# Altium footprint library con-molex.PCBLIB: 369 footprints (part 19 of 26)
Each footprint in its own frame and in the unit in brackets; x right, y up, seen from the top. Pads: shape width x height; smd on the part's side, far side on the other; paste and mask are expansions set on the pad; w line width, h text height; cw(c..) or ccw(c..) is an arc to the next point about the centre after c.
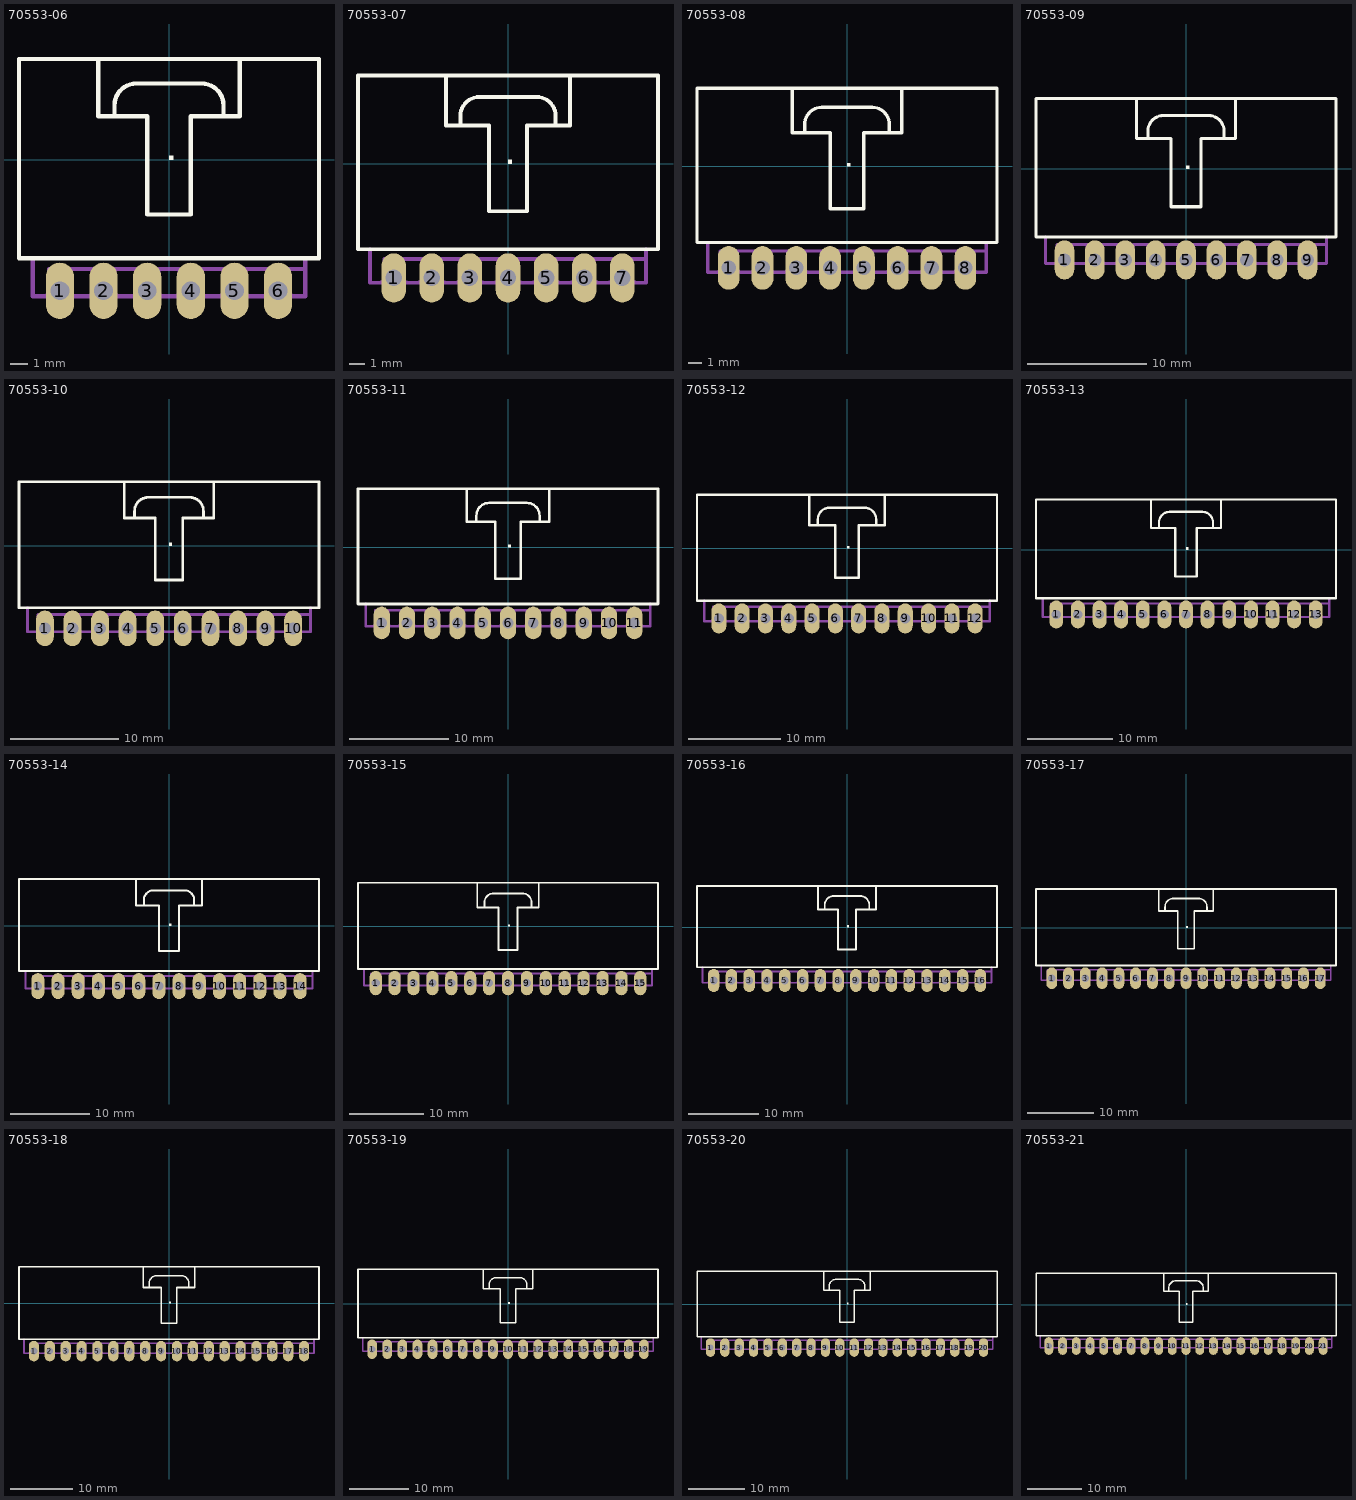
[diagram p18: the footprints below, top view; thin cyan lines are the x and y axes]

## 70553-06 [mil]
pads (6):
  oval 64.5x129 hole 43: 1(-250,-300) 2(-150,-300) 3(-50,-300) 4(50,-300) 5(150,-300) 6(250,-300)
Top Overlay:
  region: 0,0 10,0 10,10 0,10
  lines w10: -162.5,231.25 -162.5,100 -125,100 ; -125,100 -50,100 -50,-125 50,-125 50,100 125,100 ; -125,100 -125,125 cw(c-75,125) -75,175 75,175 cw(c75,125) 125,125 125,100 ; 125,100 162.5,100 162.5,231.25 ; 162.5,231.25 343.75,231.25 343.75,-225 -343.75,-225 -343.75,231.25 162.5,231.25
Mechanical 16:
  rectangle: -262.5,-300 -237.5,-250
  rectangle: -162.5,-300 -137.5,-250
  rectangle: -62.5,-300 -37.5,-250
  rectangle: 37.5,-300 62.5,-250
  rectangle: 137.5,-300 162.5,-250
  rectangle: 237.5,-300 262.5,-250
  lines w5: -275,-250 -225,-250 ; -175,-250 -125,-250 ; -75,-250 -25,-250 ; 25,-250 75,-250 ; 125,-250 175,-250 ; 225,-250 275,-250
  lines w10: -312.5,-225 -312.5,-312.5 -285,-312.5 ccw(c-285,-302.5) -275,-302.5 -275,-250 ; 312.5,-225 312.5,-250 ; 312.5,-250 312.5,-312.5 285,-312.5 cw(c285,-302.5) 275,-302.5 275,-250 312.5,-250 ; -225,-302.5 -225,-250 -175,-250 -175,-302.5 cw(c-185,-302.5) -185,-312.5 -215,-312.5 cw(c-215,-302.5) -225,-302.5 ; -125,-302.5 -125,-250 -75,-250 -75,-302.5 cw(c-85,-302.5) -85,-312.5 -115,-312.5 cw(c-115,-302.5) -125,-302.5 ; -25,-302.5 -25,-250 25,-250 25,-302.5 cw(c15,-302.5) 15,-312.5 -15,-312.5 cw(c-15,-302.5) -25,-302.5 ; 75,-302.5 75,-250 125,-250 125,-302.5 cw(c115,-302.5) 115,-312.5 85,-312.5 cw(c85,-302.5) 75,-302.5 ; 175,-302.5 175,-250 225,-250 225,-302.5 cw(c215,-302.5) 215,-312.5 185,-312.5 cw(c185,-302.5) 175,-302.5

## 70553-07 [mil]
pads (7):
  oval 64.5x129 hole 43: 1(-300,-300) 2(-200,-300) 3(-100,-300) 4(0,-300) 5(100,-300) 6(200,-300) 7(300,-300)
Top Overlay:
  region: 0,0 10,0 10,10 0,10
  lines w10: -162.5,231.25 -162.5,100 -125,100 ; -125,100 -50,100 -50,-125 50,-125 50,100 125,100 ; -125,100 -125,125 cw(c-75,125) -75,175 75,175 cw(c75,125) 125,125 125,100 ; 125,100 162.5,100 162.5,231.25 ; 162.5,231.25 393.75,231.25 393.75,-225 -393.75,-225 -393.75,231.25 162.5,231.25
Mechanical 16:
  rectangle: -312.5,-300 -287.5,-250
  rectangle: -212.5,-300 -187.5,-250
  rectangle: -112.5,-300 -87.5,-250
  rectangle: -12.5,-300 12.5,-250
  rectangle: 87.5,-300 112.5,-250
  rectangle: 187.5,-300 212.5,-250
  rectangle: 287.5,-300 312.5,-250
  lines w5: -325,-250 -275,-250 ; -225,-250 -175,-250 ; -125,-250 -75,-250 ; -25,-250 25,-250 ; 75,-250 125,-250 ; 175,-250 225,-250 ; 275,-250 325,-250
  lines w10: -362.5,-225 -362.5,-312.5 -335,-312.5 ccw(c-335,-302.5) -325,-302.5 -325,-250 ; 362.5,-225 362.5,-250 ; 362.5,-250 362.5,-312.5 335,-312.5 cw(c335,-302.5) 325,-302.5 325,-250 362.5,-250 ; -275,-302.5 -275,-250 -225,-250 -225,-302.5 cw(c-235,-302.5) -235,-312.5 -265,-312.5 cw(c-265,-302.5) -275,-302.5 ; -175,-302.5 -175,-250 -125,-250 -125,-302.5 cw(c-135,-302.5) -135,-312.5 -165,-312.5 cw(c-165,-302.5) -175,-302.5 ; -75,-302.5 -75,-250 -25,-250 -25,-302.5 cw(c-35,-302.5) -35,-312.5 -65,-312.5 cw(c-65,-302.5) -75,-302.5 ; 25,-302.5 25,-250 75,-250 75,-302.5 cw(c65,-302.5) 65,-312.5 35,-312.5 cw(c35,-302.5) 25,-302.5 ; 125,-302.5 125,-250 175,-250 175,-302.5 cw(c165,-302.5) 165,-312.5 135,-312.5 cw(c135,-302.5) 125,-302.5 ; 225,-302.5 225,-250 275,-250 275,-302.5 cw(c265,-302.5) 265,-312.5 235,-312.5 cw(c235,-302.5) 225,-302.5

## 70553-08 [mil]
pads (8):
  oval 64.5x129 hole 43: 1(-350,-300) 2(-250,-300) 3(-150,-300) 4(-50,-300) 5(50,-300) 6(150,-300) 7(250,-300) 8(350,-300)
Top Overlay:
  region: 0,0 10,0 10,10 0,10
  lines w10: -162.5,231.25 -162.5,100 -125,100 ; -125,100 -50,100 -50,-125 50,-125 50,100 125,100 ; -125,100 -125,125 cw(c-75,125) -75,175 75,175 cw(c75,125) 125,125 125,100 ; 125,100 162.5,100 162.5,231.25 ; 162.5,231.25 443.75,231.25 443.75,-225 -443.75,-225 -443.75,231.25 162.5,231.25
Mechanical 16:
  rectangle: -362.5,-300 -337.5,-250
  rectangle: -262.5,-300 -237.5,-250
  rectangle: -162.5,-300 -137.5,-250
  rectangle: -62.5,-300 -37.5,-250
  rectangle: 37.5,-300 62.5,-250
  rectangle: 137.5,-300 162.5,-250
  rectangle: 237.5,-300 262.5,-250
  rectangle: 337.5,-300 362.5,-250
  lines w5: -375,-250 -325,-250 ; -275,-250 -225,-250 ; -175,-250 -125,-250 ; -75,-250 -25,-250 ; 25,-250 75,-250 ; 125,-250 175,-250 ; 225,-250 275,-250 ; 325,-250 375,-250
  lines w10: -412.5,-225 -412.5,-312.5 -385,-312.5 ccw(c-385,-302.5) -375,-302.5 -375,-250 ; 412.5,-225 412.5,-250 ; 412.5,-250 412.5,-312.5 385,-312.5 cw(c385,-302.5) 375,-302.5 375,-250 412.5,-250 ; -325,-302.5 -325,-250 -275,-250 -275,-302.5 cw(c-285,-302.5) -285,-312.5 -315,-312.5 cw(c-315,-302.5) -325,-302.5 ; -225,-302.5 -225,-250 -175,-250 -175,-302.5 cw(c-185,-302.5) -185,-312.5 -215,-312.5 cw(c-215,-302.5) -225,-302.5 ; -125,-302.5 -125,-250 -75,-250 -75,-302.5 cw(c-85,-302.5) -85,-312.5 -115,-312.5 cw(c-115,-302.5) -125,-302.5 ; -25,-302.5 -25,-250 25,-250 25,-302.5 cw(c15,-302.5) 15,-312.5 -15,-312.5 cw(c-15,-302.5) -25,-302.5 ; 75,-302.5 75,-250 125,-250 125,-302.5 cw(c115,-302.5) 115,-312.5 85,-312.5 cw(c85,-302.5) 75,-302.5 ; 175,-302.5 175,-250 225,-250 225,-302.5 cw(c215,-302.5) 215,-312.5 185,-312.5 cw(c185,-302.5) 175,-302.5 ; 275,-302.5 275,-250 325,-250 325,-302.5 cw(c315,-302.5) 315,-312.5 285,-312.5 cw(c285,-302.5) 275,-302.5

## 70553-09 [mil]
pads (9):
  oval 64.5x129 hole 43: 1(-400,-300) 2(-300,-300) 3(-200,-300) 4(-100,-300) 5(0,-300) 6(100,-300) 7(200,-300) 8(300,-300) 9(400,-300)
Top Overlay:
  region: 0,0 10,0 10,10 0,10
  lines w10: -162.5,231.25 -162.5,100 -125,100 ; -125,100 -50,100 -50,-125 50,-125 50,100 125,100 ; -125,100 -125,125 cw(c-75,125) -75,175 75,175 cw(c75,125) 125,125 125,100 ; 125,100 162.5,100 162.5,231.25 ; 162.5,231.25 493.75,231.25 493.75,-225 -493.75,-225 -493.75,231.25 162.5,231.25
Mechanical 16:
  rectangle: -412.5,-300 -387.5,-250
  rectangle: -312.5,-300 -287.5,-250
  rectangle: -212.5,-300 -187.5,-250
  rectangle: -112.5,-300 -87.5,-250
  rectangle: -12.5,-300 12.5,-250
  rectangle: 87.5,-300 112.5,-250
  rectangle: 187.5,-300 212.5,-250
  rectangle: 287.5,-300 312.5,-250
  rectangle: 387.5,-300 412.5,-250
  lines w5: -425,-250 -375,-250 ; -325,-250 -275,-250 ; -225,-250 -175,-250 ; -125,-250 -75,-250 ; -25,-250 25,-250 ; 75,-250 125,-250 ; 175,-250 225,-250 ; 275,-250 325,-250 ; 375,-250 425,-250
  lines w10: -462.5,-225 -462.5,-312.5 -435,-312.5 ccw(c-435,-302.5) -425,-302.5 -425,-250 ; 462.5,-225 462.5,-250 ; 462.5,-250 462.5,-312.5 435,-312.5 cw(c435,-302.5) 425,-302.5 425,-250 462.5,-250 ; -375,-302.5 -375,-250 -325,-250 -325,-302.5 cw(c-335,-302.5) -335,-312.5 -365,-312.5 cw(c-365,-302.5) -375,-302.5 ; -275,-302.5 -275,-250 -225,-250 -225,-302.5 cw(c-235,-302.5) -235,-312.5 -265,-312.5 cw(c-265,-302.5) -275,-302.5 ; -175,-302.5 -175,-250 -125,-250 -125,-302.5 cw(c-135,-302.5) -135,-312.5 -165,-312.5 cw(c-165,-302.5) -175,-302.5 ; -75,-302.5 -75,-250 -25,-250 -25,-302.5 cw(c-35,-302.5) -35,-312.5 -65,-312.5 cw(c-65,-302.5) -75,-302.5 ; 25,-302.5 25,-250 75,-250 75,-302.5 cw(c65,-302.5) 65,-312.5 35,-312.5 cw(c35,-302.5) 25,-302.5 ; 125,-302.5 125,-250 175,-250 175,-302.5 cw(c165,-302.5) 165,-312.5 135,-312.5 cw(c135,-302.5) 125,-302.5 ; 225,-302.5 225,-250 275,-250 275,-302.5 cw(c265,-302.5) 265,-312.5 235,-312.5 cw(c235,-302.5) 225,-302.5 ; 325,-302.5 325,-250 375,-250 375,-302.5 cw(c365,-302.5) 365,-312.5 335,-312.5 cw(c335,-302.5) 325,-302.5

## 70553-10 [mil]
pads (10):
  oval 64.5x129 hole 43: 1(-450,-300) 2(-350,-300) 3(-250,-300) 4(-150,-300) 5(-50,-300) 6(50,-300) 7(150,-300) 8(250,-300) 9(350,-300) 10(450,-300)
Top Overlay:
  region: 0,0 10,0 10,10 0,10
  lines w10: -162.5,231.25 -162.5,100 -125,100 ; -125,100 -50,100 -50,-125 50,-125 50,100 125,100 ; -125,100 -125,125 cw(c-75,125) -75,175 75,175 cw(c75,125) 125,125 125,100 ; 125,100 162.5,100 162.5,231.25 ; 162.5,231.25 543.75,231.25 543.75,-225 -543.75,-225 -543.75,231.25 162.5,231.25
Mechanical 16:
  rectangle: -462.5,-300 -437.5,-250
  rectangle: -362.5,-300 -337.5,-250
  rectangle: -262.5,-300 -237.5,-250
  rectangle: -162.5,-300 -137.5,-250
  rectangle: -62.5,-300 -37.5,-250
  rectangle: 37.5,-300 62.5,-250
  rectangle: 137.5,-300 162.5,-250
  rectangle: 237.5,-300 262.5,-250
  rectangle: 337.5,-300 362.5,-250
  rectangle: 437.5,-300 462.5,-250
  lines w5: -475,-250 -425,-250 ; -375,-250 -325,-250 ; -275,-250 -225,-250 ; -175,-250 -125,-250 ; -75,-250 -25,-250 ; 25,-250 75,-250 ; 125,-250 175,-250 ; 225,-250 275,-250 ; 325,-250 375,-250 ; 425,-250 475,-250
  lines w10: -512.5,-225 -512.5,-312.5 -485,-312.5 ccw(c-485,-302.5) -475,-302.5 -475,-250 ; 512.5,-225 512.5,-250 ; 512.5,-250 512.5,-312.5 485,-312.5 cw(c485,-302.5) 475,-302.5 475,-250 512.5,-250 ; -425,-302.5 -425,-250 -375,-250 -375,-302.5 cw(c-385,-302.5) -385,-312.5 -415,-312.5 cw(c-415,-302.5) -425,-302.5 ; -325,-302.5 -325,-250 -275,-250 -275,-302.5 cw(c-285,-302.5) -285,-312.5 -315,-312.5 cw(c-315,-302.5) -325,-302.5 ; -225,-302.5 -225,-250 -175,-250 -175,-302.5 cw(c-185,-302.5) -185,-312.5 -215,-312.5 cw(c-215,-302.5) -225,-302.5 ; -125,-302.5 -125,-250 -75,-250 -75,-302.5 cw(c-85,-302.5) -85,-312.5 -115,-312.5 cw(c-115,-302.5) -125,-302.5 ; -25,-302.5 -25,-250 25,-250 25,-302.5 cw(c15,-302.5) 15,-312.5 -15,-312.5 cw(c-15,-302.5) -25,-302.5 ; 75,-302.5 75,-250 125,-250 125,-302.5 cw(c115,-302.5) 115,-312.5 85,-312.5 cw(c85,-302.5) 75,-302.5 ; 175,-302.5 175,-250 225,-250 225,-302.5 cw(c215,-302.5) 215,-312.5 185,-312.5 cw(c185,-302.5) 175,-302.5 ; 275,-302.5 275,-250 325,-250 325,-302.5 cw(c315,-302.5) 315,-312.5 285,-312.5 cw(c285,-302.5) 275,-302.5 ; 375,-302.5 375,-250 425,-250 425,-302.5 cw(c415,-302.5) 415,-312.5 385,-312.5 cw(c385,-302.5) 375,-302.5

## 70553-11 [mil]
pads (11):
  oval 64.5x129 hole 43: 1(-500,-300) 2(-400,-300) 3(-300,-300) 4(-200,-300) 5(-100,-300) 6(0,-300) 7(100,-300) 8(200,-300) 9(300,-300) 10(400,-300) 11(500,-300)
Top Overlay:
  region: 0,0 10,0 10,10 0,10
  lines w10: -162.5,231.25 -162.5,100 -125,100 ; -125,100 -50,100 -50,-125 50,-125 50,100 125,100 ; -125,100 -125,125 cw(c-75,125) -75,175 75,175 cw(c75,125) 125,125 125,100 ; 125,100 162.5,100 162.5,231.25 ; 162.5,231.25 593.75,231.25 593.75,-225 -593.75,-225 -593.75,231.25 162.5,231.25
Mechanical 16:
  rectangle: -512.5,-300 -487.5,-250
  rectangle: -412.5,-300 -387.5,-250
  rectangle: -312.5,-300 -287.5,-250
  rectangle: -212.5,-300 -187.5,-250
  rectangle: -112.5,-300 -87.5,-250
  rectangle: -12.5,-300 12.5,-250
  rectangle: 87.5,-300 112.5,-250
  rectangle: 187.5,-300 212.5,-250
  rectangle: 287.5,-300 312.5,-250
  rectangle: 387.5,-300 412.5,-250
  rectangle: 487.5,-300 512.5,-250
  lines w5: -525,-250 -475,-250 ; -425,-250 -375,-250 ; -325,-250 -275,-250 ; -225,-250 -175,-250 ; -125,-250 -75,-250 ; -25,-250 25,-250 ; 75,-250 125,-250 ; 175,-250 225,-250 ; 275,-250 325,-250 ; 375,-250 425,-250 ; 475,-250 525,-250
  lines w10: -562.5,-225 -562.5,-312.5 -535,-312.5 ccw(c-535,-302.5) -525,-302.5 -525,-250 ; 562.5,-225 562.5,-250 ; 562.5,-250 562.5,-312.5 535,-312.5 cw(c535,-302.5) 525,-302.5 525,-250 562.5,-250 ; -475,-302.5 -475,-250 -425,-250 -425,-302.5 cw(c-435,-302.5) -435,-312.5 -465,-312.5 cw(c-465,-302.5) -475,-302.5 ; -375,-302.5 -375,-250 -325,-250 -325,-302.5 cw(c-335,-302.5) -335,-312.5 -365,-312.5 cw(c-365,-302.5) -375,-302.5 ; -275,-302.5 -275,-250 -225,-250 -225,-302.5 cw(c-235,-302.5) -235,-312.5 -265,-312.5 cw(c-265,-302.5) -275,-302.5 ; -175,-302.5 -175,-250 -125,-250 -125,-302.5 cw(c-135,-302.5) -135,-312.5 -165,-312.5 cw(c-165,-302.5) -175,-302.5 ; -75,-302.5 -75,-250 -25,-250 -25,-302.5 cw(c-35,-302.5) -35,-312.5 -65,-312.5 cw(c-65,-302.5) -75,-302.5 ; 25,-302.5 25,-250 75,-250 75,-302.5 cw(c65,-302.5) 65,-312.5 35,-312.5 cw(c35,-302.5) 25,-302.5 ; 125,-302.5 125,-250 175,-250 175,-302.5 cw(c165,-302.5) 165,-312.5 135,-312.5 cw(c135,-302.5) 125,-302.5 ; 225,-302.5 225,-250 275,-250 275,-302.5 cw(c265,-302.5) 265,-312.5 235,-312.5 cw(c235,-302.5) 225,-302.5 ; 325,-302.5 325,-250 375,-250 375,-302.5 cw(c365,-302.5) 365,-312.5 335,-312.5 cw(c335,-302.5) 325,-302.5 ; 425,-302.5 425,-250 475,-250 475,-302.5 cw(c465,-302.5) 465,-312.5 435,-312.5 cw(c435,-302.5) 425,-302.5

## 70553-12 [mil]
pads (12):
  oval 64.5x129 hole 43: 1(-550,-300) 2(-450,-300) 3(-350,-300) 4(-250,-300) 5(-150,-300) 6(-50,-300) 7(50,-300) 8(150,-300) 9(250,-300) 10(350,-300) 11(450,-300) 12(550,-300)
Top Overlay:
  region: 0,0 10,0 10,10 0,10
  lines w10: -162.5,231.25 -162.5,100 -125,100 ; -125,100 -50,100 -50,-125 50,-125 50,100 125,100 ; -125,100 -125,125 cw(c-75,125) -75,175 75,175 cw(c75,125) 125,125 125,100 ; 125,100 162.5,100 162.5,231.25 ; 162.5,231.25 643.75,231.25 643.75,-225 -643.75,-225 -643.75,231.25 162.5,231.25
Mechanical 16:
  rectangle: -562.5,-300 -537.5,-250
  rectangle: -462.5,-300 -437.5,-250
  rectangle: -362.5,-300 -337.5,-250
  rectangle: -262.5,-300 -237.5,-250
  rectangle: -162.5,-300 -137.5,-250
  rectangle: -62.5,-300 -37.5,-250
  rectangle: 37.5,-300 62.5,-250
  rectangle: 137.5,-300 162.5,-250
  rectangle: 237.5,-300 262.5,-250
  rectangle: 337.5,-300 362.5,-250
  rectangle: 437.5,-300 462.5,-250
  rectangle: 537.5,-300 562.5,-250
  lines w5: -575,-250 -525,-250 ; -475,-250 -425,-250 ; -375,-250 -325,-250 ; -275,-250 -225,-250 ; -175,-250 -125,-250 ; -75,-250 -25,-250 ; 25,-250 75,-250 ; 125,-250 175,-250 ; 225,-250 275,-250 ; 325,-250 375,-250 ; 425,-250 475,-250 ; 525,-250 575,-250
  lines w10: -612.5,-225 -612.5,-312.5 -585,-312.5 ccw(c-585,-302.5) -575,-302.5 -575,-250 ; 612.5,-225 612.5,-250 ; 612.5,-250 612.5,-312.5 585,-312.5 cw(c585,-302.5) 575,-302.5 575,-250 612.5,-250 ; -525,-302.5 -525,-250 -475,-250 -475,-302.5 cw(c-485,-302.5) -485,-312.5 -515,-312.5 cw(c-515,-302.5) -525,-302.5 ; -425,-302.5 -425,-250 -375,-250 -375,-302.5 cw(c-385,-302.5) -385,-312.5 -415,-312.5 cw(c-415,-302.5) -425,-302.5 ; -325,-302.5 -325,-250 -275,-250 -275,-302.5 cw(c-285,-302.5) -285,-312.5 -315,-312.5 cw(c-315,-302.5) -325,-302.5 ; -225,-302.5 -225,-250 -175,-250 -175,-302.5 cw(c-185,-302.5) -185,-312.5 -215,-312.5 cw(c-215,-302.5) -225,-302.5 ; -125,-302.5 -125,-250 -75,-250 -75,-302.5 cw(c-85,-302.5) -85,-312.5 -115,-312.5 cw(c-115,-302.5) -125,-302.5 ; -25,-302.5 -25,-250 25,-250 25,-302.5 cw(c15,-302.5) 15,-312.5 -15,-312.5 cw(c-15,-302.5) -25,-302.5 ; 75,-302.5 75,-250 125,-250 125,-302.5 cw(c115,-302.5) 115,-312.5 85,-312.5 cw(c85,-302.5) 75,-302.5 ; 175,-302.5 175,-250 225,-250 225,-302.5 cw(c215,-302.5) 215,-312.5 185,-312.5 cw(c185,-302.5) 175,-302.5 ; 275,-302.5 275,-250 325,-250 325,-302.5 cw(c315,-302.5) 315,-312.5 285,-312.5 cw(c285,-302.5) 275,-302.5 ; 375,-302.5 375,-250 425,-250 425,-302.5 cw(c415,-302.5) 415,-312.5 385,-312.5 cw(c385,-302.5) 375,-302.5 ; 475,-302.5 475,-250 525,-250 525,-302.5 cw(c515,-302.5) 515,-312.5 485,-312.5 cw(c485,-302.5) 475,-302.5

## 70553-13 [mil]
pads (13):
  oval 64.5x129 hole 43: 1(-600,-300) 2(-500,-300) 3(-400,-300) 4(-300,-300) 5(-200,-300) 6(-100,-300) 7(0,-300) 8(100,-300) 9(200,-300) 10(300,-300) 11(400,-300) 12(500,-300) 13(600,-300)
Top Overlay:
  region: 0,0 10,0 10,10 0,10
  lines w10: -162.5,231.25 -162.5,100 -125,100 ; -125,100 -50,100 -50,-125 50,-125 50,100 125,100 ; -125,100 -125,125 cw(c-75,125) -75,175 75,175 cw(c75,125) 125,125 125,100 ; 125,100 162.5,100 162.5,231.25 ; 162.5,231.25 693.75,231.25 693.75,-225 -693.75,-225 -693.75,231.25 162.5,231.25
Mechanical 16:
  rectangle: -612.5,-300 -587.5,-250
  rectangle: -512.5,-300 -487.5,-250
  rectangle: -412.5,-300 -387.5,-250
  rectangle: -312.5,-300 -287.5,-250
  rectangle: -212.5,-300 -187.5,-250
  rectangle: -112.5,-300 -87.5,-250
  rectangle: -12.5,-300 12.5,-250
  rectangle: 87.5,-300 112.5,-250
  rectangle: 187.5,-300 212.5,-250
  rectangle: 287.5,-300 312.5,-250
  rectangle: 587.5,-300 612.5,-250
  rectangle: 387.5,-300 412.5,-250
  rectangle: 487.5,-300 512.5,-250
  lines w5: -625,-250 -575,-250 ; -525,-250 -475,-250 ; -425,-250 -375,-250 ; -325,-250 -275,-250 ; -225,-250 -175,-250 ; -125,-250 -75,-250 ; -25,-250 25,-250 ; 75,-250 125,-250 ; 175,-250 225,-250 ; 275,-250 325,-250 ; 375,-250 425,-250 ; 475,-250 525,-250 ; 575,-250 625,-250
  lines w10: -662.5,-225 -662.5,-312.5 -635,-312.5 ccw(c-635,-302.5) -625,-302.5 -625,-250 ; 662.5,-225 662.5,-250 ; 662.5,-250 662.5,-312.5 635,-312.5 cw(c635,-302.5) 625,-302.5 625,-250 662.5,-250 ; -575,-302.5 -575,-250 -525,-250 -525,-302.5 cw(c-535,-302.5) -535,-312.5 -565,-312.5 cw(c-565,-302.5) -575,-302.5 ; -475,-302.5 -475,-250 -425,-250 -425,-302.5 cw(c-435,-302.5) -435,-312.5 -465,-312.5 cw(c-465,-302.5) -475,-302.5 ; -375,-302.5 -375,-250 -325,-250 -325,-302.5 cw(c-335,-302.5) -335,-312.5 -365,-312.5 cw(c-365,-302.5) -375,-302.5 ; -275,-302.5 -275,-250 -225,-250 -225,-302.5 cw(c-235,-302.5) -235,-312.5 -265,-312.5 cw(c-265,-302.5) -275,-302.5 ; -175,-302.5 -175,-250 -125,-250 -125,-302.5 cw(c-135,-302.5) -135,-312.5 -165,-312.5 cw(c-165,-302.5) -175,-302.5 ; -75,-302.5 -75,-250 -25,-250 -25,-302.5 cw(c-35,-302.5) -35,-312.5 -65,-312.5 cw(c-65,-302.5) -75,-302.5 ; 25,-302.5 25,-250 75,-250 75,-302.5 cw(c65,-302.5) 65,-312.5 35,-312.5 cw(c35,-302.5) 25,-302.5 ; 125,-302.5 125,-250 175,-250 175,-302.5 cw(c165,-302.5) 165,-312.5 135,-312.5 cw(c135,-302.5) 125,-302.5 ; 225,-302.5 225,-250 275,-250 275,-302.5 cw(c265,-302.5) 265,-312.5 235,-312.5 cw(c235,-302.5) 225,-302.5 ; 325,-302.5 325,-250 375,-250 375,-302.5 cw(c365,-302.5) 365,-312.5 335,-312.5 cw(c335,-302.5) 325,-302.5 ; 425,-302.5 425,-250 475,-250 475,-302.5 cw(c465,-302.5) 465,-312.5 435,-312.5 cw(c435,-302.5) 425,-302.5 ; 525,-302.5 525,-250 575,-250 575,-302.5 cw(c565,-302.5) 565,-312.5 535,-312.5 cw(c535,-302.5) 525,-302.5

## 70553-14 [mil]
pads (14):
  oval 64.5x129 hole 43: 1(-650,-300) 2(-550,-300) 3(-450,-300) 4(-350,-300) 5(-250,-300) 6(-150,-300) 7(-50,-300) 8(50,-300) 9(150,-300) 10(250,-300) 11(350,-300) 12(450,-300) 13(550,-300) 14(650,-300)
Top Overlay:
  region: 0,0 10,0 10,10 0,10
  lines w10: -162.5,231.25 -162.5,100 -125,100 ; -125,100 -50,100 -50,-125 50,-125 50,100 125,100 ; -125,100 -125,125 cw(c-75,125) -75,175 75,175 cw(c75,125) 125,125 125,100 ; 125,100 162.5,100 162.5,231.25 ; 162.5,231.25 743.75,231.25 743.75,-225 -743.75,-225 -743.75,231.25 162.5,231.25
Mechanical 16:
  rectangle: -662.5,-300 -637.5,-250
  rectangle: -562.5,-300 -537.5,-250
  rectangle: -462.5,-300 -437.5,-250
  rectangle: -362.5,-300 -337.5,-250
  rectangle: -262.5,-300 -237.5,-250
  rectangle: -162.5,-300 -137.5,-250
  rectangle: -62.5,-300 -37.5,-250
  rectangle: 37.5,-300 62.5,-250
  rectangle: 137.5,-300 162.5,-250
  rectangle: 237.5,-300 262.5,-250
  rectangle: 637.5,-300 662.5,-250
  rectangle: 337.5,-300 362.5,-250
  rectangle: 437.5,-300 462.5,-250
  rectangle: 537.5,-300 562.5,-250
  lines w5: -675,-250 -625,-250 ; -575,-250 -525,-250 ; -475,-250 -425,-250 ; -375,-250 -325,-250 ; -275,-250 -225,-250 ; -175,-250 -125,-250 ; -75,-250 -25,-250 ; 25,-250 75,-250 ; 125,-250 175,-250 ; 225,-250 275,-250 ; 325,-250 375,-250 ; 525,-250 575,-250 ; 625,-250 675,-250
  lines w10: -712.5,-225 -712.5,-312.5 -685,-312.5 ccw(c-685,-302.5) -675,-302.5 -675,-250 ; 712.5,-225 712.5,-250 ; 425,-250 375,-250 375,-302.5 ccw(c385,-302.5) 385,-312.5 415,-312.5 ccw(c415,-302.5) 425,-302.5 425,-250 ; 425,-250 475,-250 ; 475,-250 525,-250 525,-302.5 cw(c515,-302.5) 515,-312.5 485,-312.5 cw(c485,-302.5) 475,-302.5 475,-250 ; 712.5,-250 712.5,-312.5 685,-312.5 cw(c685,-302.5) 675,-302.5 675,-250 712.5,-250 ; -625,-302.5 -625,-250 -575,-250 -575,-302.5 cw(c-585,-302.5) -585,-312.5 -615,-312.5 cw(c-615,-302.5) -625,-302.5 ; -525,-302.5 -525,-250 -475,-250 -475,-302.5 cw(c-485,-302.5) -485,-312.5 -515,-312.5 cw(c-515,-302.5) -525,-302.5 ; -425,-302.5 -425,-250 -375,-250 -375,-302.5 cw(c-385,-302.5) -385,-312.5 -415,-312.5 cw(c-415,-302.5) -425,-302.5 ; -325,-302.5 -325,-250 -275,-250 -275,-302.5 cw(c-285,-302.5) -285,-312.5 -315,-312.5 cw(c-315,-302.5) -325,-302.5 ; -225,-302.5 -225,-250 -175,-250 -175,-302.5 cw(c-185,-302.5) -185,-312.5 -215,-312.5 cw(c-215,-302.5) -225,-302.5 ; -125,-302.5 -125,-250 -75,-250 -75,-302.5 cw(c-85,-302.5) -85,-312.5 -115,-312.5 cw(c-115,-302.5) -125,-302.5 ; -25,-302.5 -25,-250 25,-250 25,-302.5 cw(c15,-302.5) 15,-312.5 -15,-312.5 cw(c-15,-302.5) -25,-302.5 ; 75,-302.5 75,-250 125,-250 125,-302.5 cw(c115,-302.5) 115,-312.5 85,-312.5 cw(c85,-302.5) 75,-302.5 ; 175,-302.5 175,-250 225,-250 225,-302.5 cw(c215,-302.5) 215,-312.5 185,-312.5 cw(c185,-302.5) 175,-302.5 ; 275,-302.5 275,-250 325,-250 325,-302.5 cw(c315,-302.5) 315,-312.5 285,-312.5 cw(c285,-302.5) 275,-302.5 ; 575,-302.5 575,-250 625,-250 625,-302.5 cw(c615,-302.5) 615,-312.5 585,-312.5 cw(c585,-302.5) 575,-302.5

## 70553-15 [mil]
pads (15):
  oval 64.5x129 hole 43: 1(-700,-300) 2(-600,-300) 3(-500,-300) 4(-400,-300) 5(-300,-300) 6(-200,-300) 7(-100,-300) 8(0,-300) 9(100,-300) 10(200,-300) 11(300,-300) 12(400,-300) 13(500,-300) 14(600,-300) 15(700,-300)
Top Overlay:
  region: 0,0 10,0 10,10 0,10
  lines w10: -162.5,231.25 -162.5,100 -125,100 ; -125,100 -50,100 -50,-125 50,-125 50,100 125,100 ; -125,100 -125,125 cw(c-75,125) -75,175 75,175 cw(c75,125) 125,125 125,100 ; 125,100 162.5,100 162.5,231.25 ; 162.5,231.25 793.75,231.25 793.75,-225 -793.75,-225 -793.75,231.25 162.5,231.25
Mechanical 16:
  rectangle: -712.5,-300 -687.5,-250
  rectangle: -612.5,-300 -587.5,-250
  rectangle: -512.5,-300 -487.5,-250
  rectangle: -412.5,-300 -387.5,-250
  rectangle: -312.5,-300 -287.5,-250
  rectangle: -212.5,-300 -187.5,-250
  rectangle: -112.5,-300 -87.5,-250
  rectangle: -12.5,-300 12.5,-250
  rectangle: 87.5,-300 112.5,-250
  rectangle: 187.5,-300 212.5,-250
  rectangle: 687.5,-300 712.5,-250
  rectangle: 287.5,-300 312.5,-250
  rectangle: 387.5,-300 412.5,-250
  rectangle: 487.5,-300 512.5,-250
  rectangle: 587.5,-300 612.5,-250
  lines w5: -725,-250 -675,-250 ; -625,-250 -575,-250 ; -525,-250 -475,-250 ; -425,-250 -375,-250 ; -325,-250 -275,-250 ; -225,-250 -175,-250 ; -125,-250 -75,-250 ; -25,-250 25,-250 ; 75,-250 125,-250 ; 175,-250 225,-250 ; 275,-250 325,-250 ; 475,-250 525,-250
  lines w10: -762.5,-225 -762.5,-312.5 -735,-312.5 ccw(c-735,-302.5) -725,-302.5 -725,-250 ; 625,-250 625,-302.5 ccw(c635,-302.5) 635,-312.5 665,-312.5 ccw(c665,-302.5) 675,-302.5 675,-250 ; 762.5,-225 762.5,-250 ; 375,-250 325,-250 325,-302.5 ccw(c335,-302.5) 335,-312.5 365,-312.5 ccw(c365,-302.5) 375,-302.5 375,-250 ; 375,-250 425,-250 ; 425,-250 475,-250 475,-302.5 cw(c465,-302.5) 465,-312.5 435,-312.5 cw(c435,-302.5) 425,-302.5 425,-250 ; 575,-250 725,-250 ; 575,-250 525,-250 525,-302.5 ccw(c535,-302.5) 535,-312.5 565,-312.5 ccw(c565,-302.5) 575,-302.5 575,-250 ; 725,-250 725,-302.5 ccw(c735,-302.5) 735,-312.5 762.5,-312.5 762.5,-250 ; 725,-250 762.5,-250 ; -675,-302.5 -675,-250 -625,-250 -625,-302.5 cw(c-635,-302.5) -635,-312.5 -665,-312.5 cw(c-665,-302.5) -675,-302.5 ; -575,-302.5 -575,-250 -525,-250 -525,-302.5 cw(c-535,-302.5) -535,-312.5 -565,-312.5 cw(c-565,-302.5) -575,-302.5 ; -475,-302.5 -475,-250 -425,-250 -425,-302.5 cw(c-435,-302.5) -435,-312.5 -465,-312.5 cw(c-465,-302.5) -475,-302.5 ; -375,-302.5 -375,-250 -325,-250 -325,-302.5 cw(c-335,-302.5) -335,-312.5 -365,-312.5 cw(c-365,-302.5) -375,-302.5 ; -275,-302.5 -275,-250 -225,-250 -225,-302.5 cw(c-235,-302.5) -235,-312.5 -265,-312.5 cw(c-265,-302.5) -275,-302.5 ; -175,-302.5 -175,-250 -125,-250 -125,-302.5 cw(c-135,-302.5) -135,-312.5 -165,-312.5 cw(c-165,-302.5) -175,-302.5 ; -75,-302.5 -75,-250 -25,-250 -25,-302.5 cw(c-35,-302.5) -35,-312.5 -65,-312.5 cw(c-65,-302.5) -75,-302.5 ; 25,-302.5 25,-250 75,-250 75,-302.5 cw(c65,-302.5) 65,-312.5 35,-312.5 cw(c35,-302.5) 25,-302.5 ; 125,-302.5 125,-250 175,-250 175,-302.5 cw(c165,-302.5) 165,-312.5 135,-312.5 cw(c135,-302.5) 125,-302.5 ; 225,-302.5 225,-250 275,-250 275,-302.5 cw(c265,-302.5) 265,-312.5 235,-312.5 cw(c235,-302.5) 225,-302.5

## 70553-16 [mil]
pads (16):
  oval 64.5x129 hole 43: 1(-750,-300) 2(-650,-300) 3(-550,-300) 4(-450,-300) 5(-350,-300) 6(-250,-300) 7(-150,-300) 8(-50,-300) 9(50,-300) 10(150,-300) 11(250,-300) 12(350,-300) 13(450,-300) 14(550,-300) 15(650,-300) 16(750,-300)
Top Overlay:
  region: 0,0 10,0 10,10 0,10
  lines w10: -162.5,231.25 -162.5,100 -125,100 ; -125,100 -50,100 -50,-125 50,-125 50,100 125,100 ; -125,100 -125,125 cw(c-75,125) -75,175 75,175 cw(c75,125) 125,125 125,100 ; 125,100 162.5,100 162.5,231.25 ; 162.5,231.25 843.75,231.25 843.75,-225 -843.75,-225 -843.75,231.25 162.5,231.25
Mechanical 16:
  rectangle: -762.5,-300 -737.5,-250
  rectangle: -662.5,-300 -637.5,-250
  rectangle: -562.5,-300 -537.5,-250
  rectangle: -462.5,-300 -437.5,-250
  rectangle: -362.5,-300 -337.5,-250
  rectangle: -262.5,-300 -237.5,-250
  rectangle: -162.5,-300 -137.5,-250
  rectangle: -62.5,-300 -37.5,-250
  rectangle: 37.5,-300 62.5,-250
  rectangle: 137.5,-300 162.5,-250
  rectangle: 737.5,-300 762.5,-250
  rectangle: 237.5,-300 262.5,-250
  rectangle: 337.5,-300 362.5,-250
  rectangle: 437.5,-300 462.5,-250
  rectangle: 537.5,-300 562.5,-250
  rectangle: 637.5,-300 662.5,-250
  lines w5: -775,-250 -725,-250 ; -675,-250 -625,-250 ; -575,-250 -525,-250 ; -475,-250 -425,-250 ; -375,-250 -325,-250 ; -275,-250 -225,-250 ; -175,-250 -125,-250 ; -75,-250 -25,-250 ; 25,-250 75,-250 ; 125,-250 175,-250 ; 225,-250 275,-250 ; 425,-250 475,-250 ; 725,-250 775,-250
  lines w10: -812.5,-225 -812.5,-312.5 -785,-312.5 ccw(c-785,-302.5) -775,-302.5 -775,-250 ; 575,-250 575,-302.5 ccw(c585,-302.5) 585,-312.5 615,-312.5 ccw(c615,-302.5) 625,-302.5 625,-250 ; 812.5,-225 812.5,-250 ; 325,-250 275,-250 275,-302.5 ccw(c285,-302.5) 285,-312.5 315,-312.5 ccw(c315,-302.5) 325,-302.5 325,-250 ; 325,-250 375,-250 ; 375,-250 425,-250 425,-302.5 cw(c415,-302.5) 415,-312.5 385,-312.5 cw(c385,-302.5) 375,-302.5 375,-250 ; 525,-250 675,-250 ; 525,-250 475,-250 475,-302.5 ccw(c485,-302.5) 485,-312.5 515,-312.5 ccw(c515,-302.5) 525,-302.5 525,-250 ; 675,-250 725,-250 725,-302.5 cw(c715,-302.5) 715,-312.5 685,-312.5 cw(c685,-302.5) 675,-302.5 675,-250 ; 812.5,-250 812.5,-312.5 785,-312.5 cw(c785,-302.5) 775,-302.5 775,-250 812.5,-250 ; -725,-302.5 -725,-250 -675,-250 -675,-302.5 cw(c-685,-302.5) -685,-312.5 -715,-312.5 cw(c-715,-302.5) -725,-302.5 ; -625,-302.5 -625,-250 -575,-250 -575,-302.5 cw(c-585,-302.5) -585,-312.5 -615,-312.5 cw(c-615,-302.5) -625,-302.5 ; -525,-302.5 -525,-250 -475,-250 -475,-302.5 cw(c-485,-302.5) -485,-312.5 -515,-312.5 cw(c-515,-302.5) -525,-302.5 ; -425,-302.5 -425,-250 -375,-250 -375,-302.5 cw(c-385,-302.5) -385,-312.5 -415,-312.5 cw(c-415,-302.5) -425,-302.5 ; -325,-302.5 -325,-250 -275,-250 -275,-302.5 cw(c-285,-302.5) -285,-312.5 -315,-312.5 cw(c-315,-302.5) -325,-302.5 ; -225,-302.5 -225,-250 -175,-250 -175,-302.5 cw(c-185,-302.5) -185,-312.5 -215,-312.5 cw(c-215,-302.5) -225,-302.5 ; -125,-302.5 -125,-250 -75,-250 -75,-302.5 cw(c-85,-302.5) -85,-312.5 -115,-312.5 cw(c-115,-302.5) -125,-302.5 ; -25,-302.5 -25,-250 25,-250 25,-302.5 cw(c15,-302.5) 15,-312.5 -15,-312.5 cw(c-15,-302.5) -25,-302.5 ; 75,-302.5 75,-250 125,-250 125,-302.5 cw(c115,-302.5) 115,-312.5 85,-312.5 cw(c85,-302.5) 75,-302.5 ; 175,-302.5 175,-250 225,-250 225,-302.5 cw(c215,-302.5) 215,-312.5 185,-312.5 cw(c185,-302.5) 175,-302.5

## 70553-17 [mil]
pads (17):
  oval 64.5x129 hole 43: 1(-800,-300) 2(-700,-300) 3(-600,-300) 4(-500,-300) 5(-400,-300) 6(-300,-300) 7(-200,-300) 8(-100,-300) 9(0,-300) 10(100,-300) 11(200,-300) 12(300,-300) 13(400,-300) 14(500,-300) 15(600,-300) 16(700,-300) 17(800,-300)
Top Overlay:
  region: 0,0 10,0 10,10 0,10
  lines w10: -162.5,231.25 -162.5,100 -125,100 ; -125,100 -50,100 -50,-125 50,-125 50,100 125,100 ; -125,100 -125,125 cw(c-75,125) -75,175 75,175 cw(c75,125) 125,125 125,100 ; 125,100 162.5,100 162.5,231.25 ; 162.5,231.25 893.75,231.25 893.75,-225 -893.75,-225 -893.75,231.25 162.5,231.25
Mechanical 16:
  rectangle: -812.5,-300 -787.5,-250
  rectangle: -712.5,-300 -687.5,-250
  rectangle: -612.5,-300 -587.5,-250
  rectangle: -512.5,-300 -487.5,-250
  rectangle: -412.5,-300 -387.5,-250
  rectangle: -312.5,-300 -287.5,-250
  rectangle: -212.5,-300 -187.5,-250
  rectangle: -112.5,-300 -87.5,-250
  rectangle: -12.5,-300 12.5,-250
  rectangle: 87.5,-300 112.5,-250
  rectangle: 787.5,-300 812.5,-250
  rectangle: 187.5,-300 212.5,-250
  rectangle: 287.5,-300 312.5,-250
  rectangle: 387.5,-300 412.5,-250
  rectangle: 487.5,-300 512.5,-250
  rectangle: 587.5,-300 612.5,-250
  rectangle: 687.5,-300 712.5,-250
  lines w5: -825,-250 -775,-250 ; -725,-250 -675,-250 ; -625,-250 -575,-250 ; -525,-250 -475,-250 ; -425,-250 -375,-250 ; -325,-250 -275,-250 ; -225,-250 -175,-250 ; -125,-250 -75,-250 ; -25,-250 25,-250 ; 75,-250 125,-250 ; 175,-250 225,-250 ; 375,-250 425,-250 ; 675,-250 725,-250 ; 775,-250 825,-250
  lines w10: -862.5,-225 -862.5,-312.5 -835,-312.5 ccw(c-835,-302.5) -825,-302.5 -825,-250 ; 525,-250 525,-302.5 ccw(c535,-302.5) 535,-312.5 565,-312.5 ccw(c565,-302.5) 575,-302.5 575,-250 ; 862.5,-225 862.5,-250 ; 275,-250 225,-250 225,-302.5 ccw(c235,-302.5) 235,-312.5 265,-312.5 ccw(c265,-302.5) 275,-302.5 275,-250 ; 275,-250 325,-250 ; 325,-250 375,-250 375,-302.5 cw(c365,-302.5) 365,-312.5 335,-312.5 cw(c335,-302.5) 325,-302.5 325,-250 ; 475,-250 625,-250 ; 475,-250 425,-250 425,-302.5 ccw(c435,-302.5) 435,-312.5 465,-312.5 ccw(c465,-302.5) 475,-302.5 475,-250 ; 625,-250 675,-250 675,-302.5 cw(c665,-302.5) 665,-312.5 635,-312.5 cw(c635,-302.5) 625,-302.5 625,-250 ; 862.5,-250 862.5,-312.5 835,-312.5 cw(c835,-302.5) 825,-302.5 825,-250 862.5,-250 ; -775,-302.5 -775,-250 -725,-250 -725,-302.5 cw(c-735,-302.5) -735,-312.5 -765,-312.5 cw(c-765,-302.5) -775,-302.5 ; -675,-302.5 -675,-250 -625,-250 -625,-302.5 cw(c-635,-302.5) -635,-312.5 -665,-312.5 cw(c-665,-302.5) -675,-302.5 ; -575,-302.5 -575,-250 -525,-250 -525,-302.5 cw(c-535,-302.5) -535,-312.5 -565,-312.5 cw(c-565,-302.5) -575,-302.5 ; -475,-302.5 -475,-250 -425,-250 -425,-302.5 cw(c-435,-302.5) -435,-312.5 -465,-312.5 cw(c-465,-302.5) -475,-302.5 ; -375,-302.5 -375,-250 -325,-250 -325,-302.5 cw(c-335,-302.5) -335,-312.5 -365,-312.5 cw(c-365,-302.5) -375,-302.5 ; -275,-302.5 -275,-250 -225,-250 -225,-302.5 cw(c-235,-302.5) -235,-312.5 -265,-312.5 cw(c-265,-302.5) -275,-302.5 ; -175,-302.5 -175,-250 -125,-250 -125,-302.5 cw(c-135,-302.5) -135,-312.5 -165,-312.5 cw(c-165,-302.5) -175,-302.5 ; -75,-302.5 -75,-250 -25,-250 -25,-302.5 cw(c-35,-302.5) -35,-312.5 -65,-312.5 cw(c-65,-302.5) -75,-302.5 ; 25,-302.5 25,-250 75,-250 75,-302.5 cw(c65,-302.5) 65,-312.5 35,-312.5 cw(c35,-302.5) 25,-302.5 ; 125,-302.5 125,-250 175,-250 175,-302.5 cw(c165,-302.5) 165,-312.5 135,-312.5 cw(c135,-302.5) 125,-302.5 ; 725,-302.5 725,-250 775,-250 775,-302.5 cw(c765,-302.5) 765,-312.5 735,-312.5 cw(c735,-302.5) 725,-302.5

## 70553-18 [mil]
pads (18):
  oval 64.5x129 hole 43: 1(-850,-300) 2(-750,-300) 3(-650,-300) 4(-550,-300) 5(-450,-300) 6(-350,-300) 7(-250,-300) 8(-150,-300) 9(-50,-300) 10(50,-300) 11(150,-300) 12(250,-300) 13(350,-300) 14(450,-300) 15(550,-300) 16(650,-300) 17(750,-300) 18(850,-300)
Top Overlay:
  region: 0,0 10,0 10,10 0,10
  lines w10: -162.5,231.25 -162.5,100 -125,100 ; -125,100 -50,100 -50,-125 50,-125 50,100 125,100 ; -125,100 -125,125 cw(c-75,125) -75,175 75,175 cw(c75,125) 125,125 125,100 ; 125,100 162.5,100 162.5,231.25 ; 162.5,231.25 943.75,231.25 943.75,-225 -943.75,-225 -943.75,231.25 162.5,231.25
Mechanical 16:
  rectangle: -862.5,-300 -837.5,-250
  rectangle: -762.5,-300 -737.5,-250
  rectangle: -662.5,-300 -637.5,-250
  rectangle: -562.5,-300 -537.5,-250
  rectangle: -462.5,-300 -437.5,-250
  rectangle: -362.5,-300 -337.5,-250
  rectangle: -262.5,-300 -237.5,-250
  rectangle: -162.5,-300 -137.5,-250
  rectangle: -62.5,-300 -37.5,-250
  rectangle: 37.5,-300 62.5,-250
  rectangle: 837.5,-300 862.5,-250
  rectangle: 137.5,-300 162.5,-250
  rectangle: 237.5,-300 262.5,-250
  rectangle: 337.5,-300 362.5,-250
  rectangle: 437.5,-300 462.5,-250
  rectangle: 537.5,-300 562.5,-250
  rectangle: 637.5,-300 662.5,-250
  rectangle: 737.5,-300 762.5,-250
  lines w5: -875,-250 -825,-250 ; -775,-250 -725,-250 ; -675,-250 -625,-250 ; -575,-250 -525,-250 ; -475,-250 -425,-250 ; -375,-250 -325,-250 ; -275,-250 -225,-250 ; -175,-250 -125,-250 ; -75,-250 -25,-250 ; 25,-250 75,-250 ; 125,-250 175,-250 ; 325,-250 375,-250 ; 625,-250 675,-250 ; 725,-250 775,-250 ; 825,-250 875,-250
  lines w10: -912.5,-225 -912.5,-312.5 -885,-312.5 ccw(c-885,-302.5) -875,-302.5 -875,-250 ; 475,-250 475,-302.5 ccw(c485,-302.5) 485,-312.5 515,-312.5 ccw(c515,-302.5) 525,-302.5 525,-250 ; 912.5,-225 912.5,-250 ; 225,-250 175,-250 175,-302.5 ccw(c185,-302.5) 185,-312.5 215,-312.5 ccw(c215,-302.5) 225,-302.5 225,-250 ; 225,-250 275,-250 ; 275,-250 325,-250 325,-302.5 cw(c315,-302.5) 315,-312.5 285,-312.5 cw(c285,-302.5) 275,-302.5 275,-250 ; 425,-250 575,-250 ; 425,-250 375,-250 375,-302.5 ccw(c385,-302.5) 385,-312.5 415,-312.5 ccw(c415,-302.5) 425,-302.5 425,-250 ; 575,-250 625,-250 625,-302.5 cw(c615,-302.5) 615,-312.5 585,-312.5 cw(c585,-302.5) 575,-302.5 575,-250 ; 912.5,-250 912.5,-312.5 885,-312.5 cw(c885,-302.5) 875,-302.5 875,-250 912.5,-250 ; -825,-302.5 -825,-250 -775,-250 -775,-302.5 cw(c-785,-302.5) -785,-312.5 -815,-312.5 cw(c-815,-302.5) -825,-302.5 ; -725,-302.5 -725,-250 -675,-250 -675,-302.5 cw(c-685,-302.5) -685,-312.5 -715,-312.5 cw(c-715,-302.5) -725,-302.5 ; -625,-302.5 -625,-250 -575,-250 -575,-302.5 cw(c-585,-302.5) -585,-312.5 -615,-312.5 cw(c-615,-302.5) -625,-302.5 ; -525,-302.5 -525,-250 -475,-250 -475,-302.5 cw(c-485,-302.5) -485,-312.5 -515,-312.5 cw(c-515,-302.5) -525,-302.5 ; -425,-302.5 -425,-250 -375,-250 -375,-302.5 cw(c-385,-302.5) -385,-312.5 -415,-312.5 cw(c-415,-302.5) -425,-302.5 ; -325,-302.5 -325,-250 -275,-250 -275,-302.5 cw(c-285,-302.5) -285,-312.5 -315,-312.5 cw(c-315,-302.5) -325,-302.5 ; -225,-302.5 -225,-250 -175,-250 -175,-302.5 cw(c-185,-302.5) -185,-312.5 -215,-312.5 cw(c-215,-302.5) -225,-302.5 ; -125,-302.5 -125,-250 -75,-250 -75,-302.5 cw(c-85,-302.5) -85,-312.5 -115,-312.5 cw(c-115,-302.5) -125,-302.5 ; -25,-302.5 -25,-250 25,-250 25,-302.5 cw(c15,-302.5) 15,-312.5 -15,-312.5 cw(c-15,-302.5) -25,-302.5 ; 75,-302.5 75,-250 125,-250 125,-302.5 cw(c115,-302.5) 115,-312.5 85,-312.5 cw(c85,-302.5) 75,-302.5 ; 675,-302.5 675,-250 725,-250 725,-302.5 cw(c715,-302.5) 715,-312.5 685,-312.5 cw(c685,-302.5) 675,-302.5 ; 775,-302.5 775,-250 825,-250 825,-302.5 cw(c815,-302.5) 815,-312.5 785,-312.5 cw(c785,-302.5) 775,-302.5

## 70553-19 [mil]
pads (19):
  oval 64.5x129 hole 43: 1(-900,-300) 2(-800,-300) 3(-700,-300) 4(-600,-300) 5(-500,-300) 6(-400,-300) 7(-300,-300) 8(-200,-300) 9(-100,-300) 10(0,-300) 11(100,-300) 12(200,-300) 13(300,-300) 14(400,-300) 15(500,-300) 16(600,-300) 17(700,-300) 18(800,-300) 19(900,-300)
Top Overlay:
  region: 0,0 10,0 10,10 0,10
  lines w10: -162.5,231.25 -162.5,100 -125,100 ; -125,100 -50,100 -50,-125 50,-125 50,100 125,100 ; -125,100 -125,125 cw(c-75,125) -75,175 75,175 cw(c75,125) 125,125 125,100 ; 125,100 162.5,100 162.5,231.25 ; 162.5,231.25 993.75,231.25 993.75,-225 -993.75,-225 -993.75,231.25 162.5,231.25
Mechanical 16:
  drawing of 154 lines, arcs and shapes, not listed

## 70553-20 [mil]
pads (20):
  oval 64.5x129 hole 43: 1(-950,-300) 2(-850,-300) 3(-750,-300) 4(-650,-300) 5(-550,-300) 6(-450,-300) 7(-350,-300) 8(-250,-300) 9(-150,-300) 10(-50,-300) 11(50,-300) 12(150,-300) 13(250,-300) 14(350,-300) 15(450,-300) 16(550,-300) 17(650,-300) 18(750,-300) 19(850,-300) 20(950,-300)
Top Overlay:
  region: 0,0 10,0 10,10 0,10
  lines w10: -162.5,231.25 -162.5,100 -125,100 ; -125,100 -50,100 -50,-125 50,-125 50,100 125,100 ; -125,100 -125,125 cw(c-75,125) -75,175 75,175 cw(c75,125) 125,125 125,100 ; 125,100 162.5,100 162.5,231.25 ; 162.5,231.25 1043.75,231.25 1043.75,-225 -1043.75,-225 -1043.75,231.25 162.5,231.25
Mechanical 16:
  drawing of 162 lines, arcs and shapes, not listed

## 70553-21 [mil]
pads (21):
  oval 64.5x129 hole 43: 1(-1000,-300) 2(-900,-300) 3(-800,-300) 4(-700,-300) 5(-600,-300) 6(-500,-300) 7(-400,-300) 8(-300,-300) 9(-200,-300) 10(-100,-300) 11(0,-300) 12(100,-300) 13(200,-300) 14(300,-300) 15(400,-300) 16(500,-300) 17(600,-300) 18(700,-300) 19(800,-300) 20(900,-300) 21(1000,-300)
Top Overlay:
  region: 0,0 10,0 10,10 0,10
  lines w10: -162.5,231.25 -162.5,100 -125,100 ; -125,100 -50,100 -50,-125 50,-125 50,100 125,100 ; -125,100 -125,125 cw(c-75,125) -75,175 75,175 cw(c75,125) 125,125 125,100 ; 125,100 162.5,100 162.5,231.25 ; 162.5,231.25 1093.75,231.25 1093.75,-225 -1093.75,-225 -1093.75,231.25 162.5,231.25
Mechanical 16:
  drawing of 170 lines, arcs and shapes, not listed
